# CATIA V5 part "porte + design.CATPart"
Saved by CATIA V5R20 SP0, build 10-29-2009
Part number: porte
Bounding box of the stored display mesh (mm): x -40 to 0, y 0 to 270, z 0 to 360
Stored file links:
  C:\Users\bensf\Desktop\bouthaina\amine.CATPart
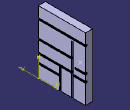
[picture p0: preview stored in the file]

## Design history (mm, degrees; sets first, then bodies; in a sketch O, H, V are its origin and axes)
Body1 (main body)
  Sketch1 on yz-plane, origin (0, 0, 0), H (0, 1, 0), V (0, 0, 1)
    line L1 (0, 0) -> (270, 0)
    line L2 (270, 0) -> (270, 360)
    line L3 (270, 360) -> (0, 360)
    line L4 (0, 360) -> (0, 0)
    length L4 = 360
    length L1 = 270
    horizontal: L1 H, L3 H
    vertical: L2 V, L4 V
  Pad1: profile Sketch1, direction (-1, 0, 0), length 40
  Sketch2 on start face of Pad1, origin (0, 0, 0), H (0, 1, 0), V (0, 0, 1)
    line L1 (270, 300) -> (0, 300)
    line L2 (0, 300) -> (0, 290)
    line L3 (0, 290) -> (270, 290)
    line L4 (270, 290) -> (270, 300)
    point P3 (0, 290)
    horizontal: L1 H, L3 H
    vertical: L2 V, L4 V
    coincidence: P3 V
  Pocket1: profile Sketch2, direction (-1, 0, 0), length 8
  Sketch3 on start face of Pad1, origin (0, 0, 0), H (0, 0, 1), V (0, -1, 0)
  Sketch4 on start face of Pad1, origin (0, 0, 0), H (0, 1, 0), V (0, 0, 1)
    line L1 (200, 280) -> (190, 280)
    line L2 (190, 280) -> (190, 0)
    line L3 (190, 0) -> (200, 0)
    line L4 (200, 0) -> (200, 280)
    point P3 (190, 0)
    horizontal: L1 H, L3 H
    vertical: L2 V, L4 V
    coincidence: P3 H
  Pocket2: profile Sketch4, direction (-1, 0, 0), length 8
  DatumSurface1
  Sketch5 on start face of Pad1, origin (0, 0, 0), H (0, 1, 0), V (0, 0, 1)
    line L1 (190, 200) -> (0, 200)
    line L2 (0, 200) -> (0, 190)
    line L3 (0, 190) -> (190, 190)
    line L4 (190, 190) -> (190, 200)
    point P3 (0, 190)
    line L5 (210, 160) -> (270, 160)
    line L6 (270, 160) -> (270, 150)
    line L7 (270, 150) -> (210, 150)
    line L8 (210, 150) -> (210, 160)
    line L9 (200, 120) -> (270, 120)
    line L10 (270, 120) -> (270, 110)
    line L11 (270, 110) -> (200, 110)
    line L12 (200, 110) -> (200, 120)
    point P11 (270, 110)
    point P13 (190, 130)
    line L13 (190, 130) -> (0, 130)
    line L14 (0, 130) -> (0, 120)
    line L15 (0, 120) -> (190, 120)
    line L16 (190, 120) -> (190, 130)
    point P15 (0, 120)
    point P17 (120, 120)
    line L17 (120, 120) -> (130, 120)
    line L18 (130, 120) -> (130, 0)
    line L19 (130, 0) -> (120, 0)
    line L20 (120, 0) -> (120, 120)
    point P19 (130, 0)
    point P21 (120, 80)
    line L21 (120, 80) -> (0, 80)
    line L22 (0, 80) -> (0, 70)
    line L23 (0, 70) -> (120, 70)
    line L24 (120, 70) -> (120, 80)
    point P23 (0, 70)
    horizontal: L1 H, L3 H, L5 H, L7 H, L9 H, L11 H, L13 H, L15 H, L17 H, L19 H, L21 H, L23 H
    vertical: L2 V, L4 V, L6 V, L8 V, L10 V, L12 V, L14 V, L16 V, L18 V, L20 V, L22 V, L24 V
    coincidence: P3 V, P11 L6, P13 L4, P15 L9, P15 V, P17 L15, P19 H, P21 L20, P23 V
  Pocket3: profile Sketch5, direction (-1, 0, 0), length 8
  Sketch6 on start face of Pad1, origin (0, 0, 0), H (0, 1, 0), V (0, 0, 1)
    point P1 (240, 200)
